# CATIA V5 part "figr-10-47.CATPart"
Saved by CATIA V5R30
Part number: Part1
Bounding box of the stored display mesh (mm): x 0 to 149.165, y -56.328 to 246, z -79.956 to 99.365
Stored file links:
  D:\PROJECTS\CATIA V56R 2020\Resources\Parts File\c10_catia_v5_6r2020_prt\figr-10-47.CATPart
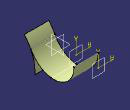
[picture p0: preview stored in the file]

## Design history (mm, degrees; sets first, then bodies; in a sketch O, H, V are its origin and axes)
Body1 (main body)
  Sketch1 on yz-plane, origin (0, 0, 0), H (0, 1, 0), V (0, 0, 1)
    arc A1 centre (-231.2925, -65.467) radius 240.3792 from (-56.3278, 99.3648) to (8.6496, -79.9559) cw
    coincidence: A1 O
  Extrude1: Element1 Sketch1, Lim1 149, Lim2 0
  Sketch2 on zx-plane, origin (0, 0, 0), H (-1, 0, 0), V (0, 0, 1)
    line L1 (-147.95, 52.1519) -> (0, 52.1519)
    point P1 (0, 52.1519)
    coincidence: P1 V
    horizontal: L1 H
  Project1: ToProject Sketch2, Support Extrude1
  Plane1: type Offset, RefPlane zx-plane, Offset 110
  Plane2: type Offset, RefPlane Plane1, Offset 136
  Sketch3 on Plane1, origin (0, 110, 0), H (-1, 0, 0), V (0, 0, 1)
    line L1 (-149.1647, -46.834) -> (0, -46.834)
    point P1 (0, -46.834)
    coincidence: P1 V
    horizontal: L1 H
  Sketch4 on Plane2, origin (0, 246, 0), H (-1, 0, 0), V (0, 0, 1)
    line L1 (-148.4227, 79.0713) -> (0, 79.0713)
    point P1 (0, 79.0713)
    coincidence: P1 V
    horizontal: L1 H
  Sweep1: type Conic, Guide ({sweepconicextendedguide Guide Project1, Reference Extrude1, Angle 0}; Sketch3; {sweepconicextendedguide Guide Sketch4, Reference Plane2, Angle 0})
